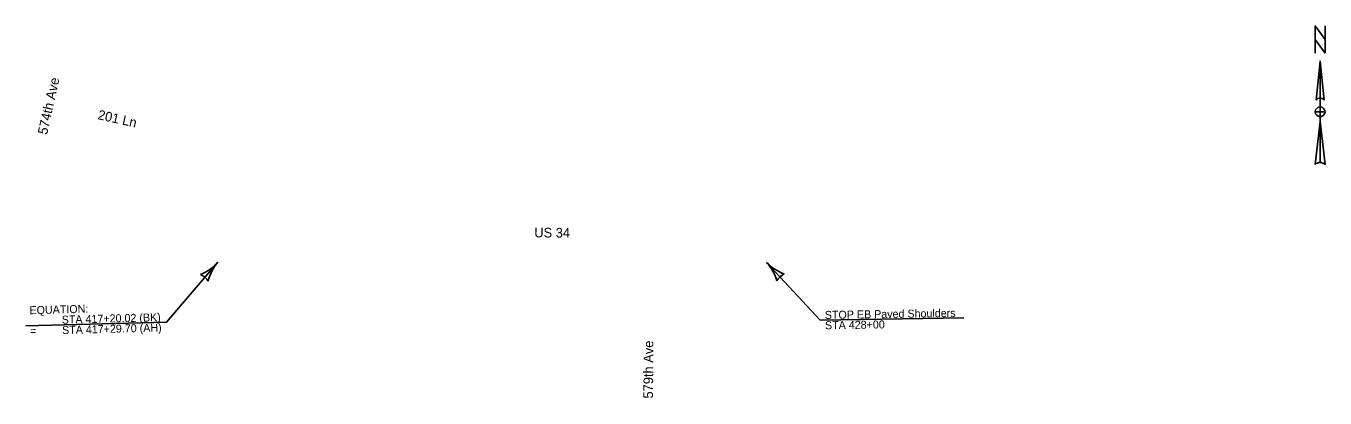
# Model space of a CAD drawing. Extents: x 22712865 to 22760106, y 6235088 to 6238602.
# Drawn here: x 22719035 to 22721568, y 6235500 to 6236226 of the extents above; entities that cross this region are included whole.
import ezdxf

# ---------------------------------------------------------------- set-up
doc = ezdxf.new("R2010")
doc.units = 0
for name, color, linetype in [('Contours Major', 7, 'Continuous'), ('Default', 7, 'Continuous'), ('Draft_3', 7, 'Continuous'), ('dsnTextOdd', 7, 'Continuous')]:
    doc.layers.add(name, color=color, linetype=linetype)

msp = doc.modelspace()

# ---------------------------------------------------------------- linework, layer by layer
at = {"layer": 'Contours Major'}
msp.add_lwpolyline([(22719408.5, 6235765), (22719308.6, 6235648.1), (22719034.5, 6235640.8)], dxfattribs=at)
for centre, radius, start, end in [((22719343.8, 6235820.2), 85, 291.4467, 319.5192), ((22719473.1, 6235709.8), 85, 139.5192, 167.5917), ((22719362.2, 6235710.8), 32.8, 31.7858, 67.2525)]:
    msp.add_arc(centre, radius, start, end, dxfattribs=at)
at = {"layer": 'Draft_3'}
msp.add_lwpolyline([(22720478.7, 6235764.5), (22720583.3, 6235651.9), (22720863.1, 6235656.2)], dxfattribs=at)
for centre, radius, start, end in [((22720416.4, 6235706.7), 85, 14.8052, 42.8777), ((22720541, 6235822.4), 85, 222.8777, 250.9502), ((22720527.2, 6235712.3), 32.8, 115.1444, 150.6111)]:
    msp.add_arc(centre, radius, start, end, dxfattribs=at)
at = {"layer": 'dsnTextOdd'}
for p, q in [((22721558.1, 6236157.1), (22721565.7, 6236081.1)), ((22721558.1, 6236157.1), (22721558.1, 6235959.4)), ((22721550.5, 6236081.1), (22721550.5, 6236081.1)), ((22721550.8, 6236081.8), (22721552.2, 6236083.4)), ((22721558.1, 6236048.7), (22721558.1, 6236048.7)), ((22721548.6, 6235955.6), (22721558.1, 6236039.2))]:
    msp.add_line(p, q, dxfattribs=at)
msp.add_lwpolyline([(22721567.6, 6236172.3), (22721548.6, 6236199), (22721548.6, 6236225.6), (22721567.6, 6236199)], close=True, dxfattribs=at)
for points in [[(22721548.6, 6236172.3), (22721548.6, 6236225.6), (22721567.6, 6236199), (22721567.6, 6236225.6)], [(22721550.5, 6236081.1), (22721558.1, 6236157.1), (22721558.1, 6236084.9)], [(22721558.1, 6236048.7), (22721558.1, 6236058.2), (22721548.6, 6236058.2)], [(22721567.6, 6236058.2), (22721558.1, 6236058.2), (22721558.1, 6236067.8)], [(22721558.1, 6235959.4), (22721558.1, 6236039.2), (22721567.6, 6235955.6)]]:
    msp.add_lwpolyline(points, dxfattribs=at)
for centre, radius, start, end in [((22721558.1, 6236075.4), 9.51, 90.0204, 143.1257), ((22721558.1, 6236075.4), 9.5, 36.8481, 90.0218), ((22721558.1, 6236058.2), 9.51, 90, 180), ((22721558.1, 6236058.2), 9.51, 180, 270), ((22721558.1, 6236058.2), 9.51, 0, 90), ((22721558.1, 6236058.2), 9.51, 270, 360), ((22721558.1, 6235945.6), 13.8, 89.9894, 133.619), ((22721558.1, 6235945.6), 13.8, 46.4021, 90.0006)]:
    msp.add_arc(centre, radius, start, end, dxfattribs=at)

# ---------------------------------------------------------------- texts
at = {"layer": 'Contours Major'}
for s, height, p in [('EQUATION:', 15.6, (22719041.6, 6235663.5)), ('STA 417+20.02 (BK)', 15.601, (22719104.5, 6235645)), ('STA 417+29.70 (AH)', 15.601, (22719105.1, 6235624.8)), ('=', 15.6, (22719042.7, 6235623.1))]:
    msp.add_text(s, height=height, rotation=1.5081, dxfattribs=at).set_placement(p)
at = {"layer": 'Default'}
for s, rotation, p in [('574th Ave', 77.4475, (22719075.5, 6236012.6)), ('201 Ln', 347.4475, (22719173.4, 6236044.1)), ('US 34', 359.6185, (22720025.7, 6235813.4)), ('579th Ave', 89.6185, (22720257.2, 6235499.1))]:
    msp.add_text(s, height=18.75, rotation=rotation, dxfattribs=at).set_placement(p)
at = {"layer": 'Draft_3'}
for s, height, p in [('STOP EB Paved Shoulders', 15.601, (22720592.3, 6235654.3)), ('STA 428+00', 15.6, (22720592.7, 6235634.1))]:
    msp.add_text(s, height=height, rotation=0.8888, dxfattribs=at).set_placement(p)

doc.saveas('drawing.dxf')
